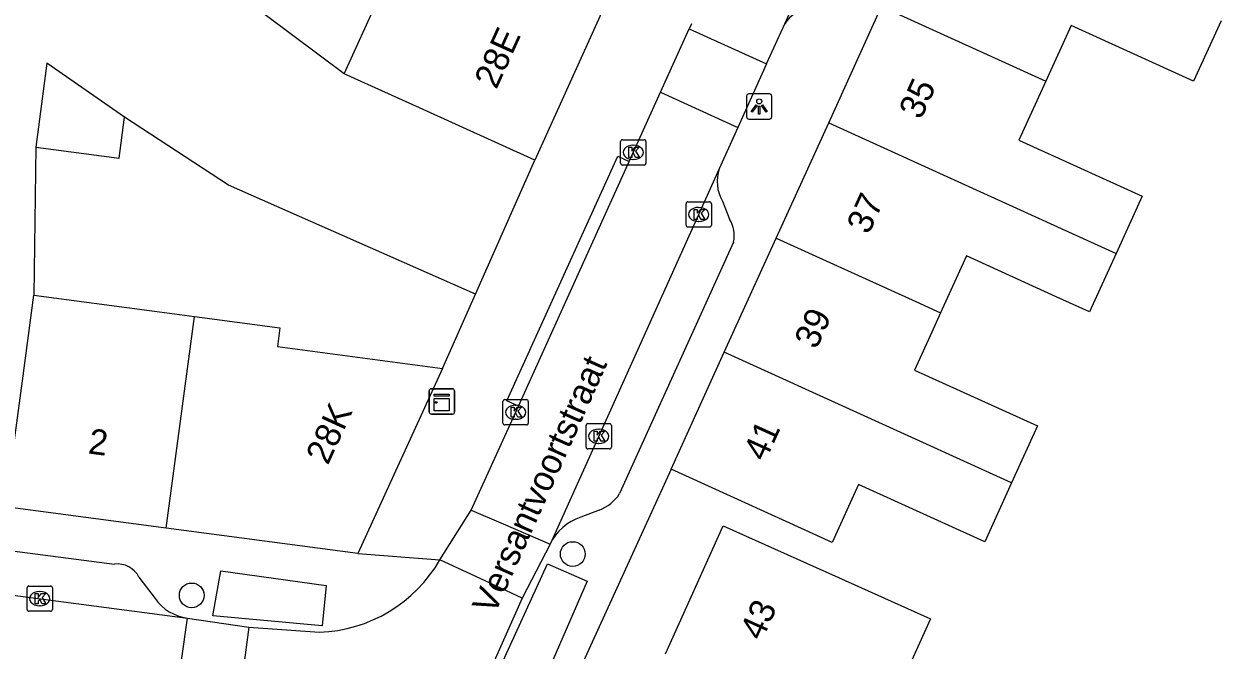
# Model space of a CAD drawing. Extents: x 161845 to 162341, y 381620 to 382158.
# Drawn here: x 162036.15 to 162083.32, y 381694.14 to 381718.91 of the extents above; entities that cross this region are included whole.
import ezdxf

# ---------------------------------------------------------------- set-up
doc = ezdxf.new("R2010")
doc.units = 0
for name, color, linetype in [('IMGEO_Boom', 7, 'Continuous'), ('IMGEO_Kast', 7, 'Continuous'), ('IMGEO_Kolk', 7, 'Continuous'), ('IMGEO_Lichtpunt', 7, 'Continuous'), ('IMGEO_Openbare_ruimte_label', 7, 'Continuous'), ('IMGEO_Pand', 7, 'Continuous'), ('IMGEO_Pand_nummerreeks', 7, 'Continuous'), ('IMGEO_Rijbaan_lokaal_open', 7, 'Continuous'), ('IMGEO_Voetpad_open', 7, 'Continuous')]:
    doc.layers.add(name, color=color, linetype=linetype)

msp = doc.modelspace()

# ---------------------------------------------------------------- linework, layer by layer
at = {"layer": 'IMGEO_Boom'}
for centre in [(162057.851, 381697.943), (162042.788, 381696.309)]:
    msp.add_circle(centre, 0.489, dxfattribs=at)
at = {"layer": 'IMGEO_Kast'}
for p, q in [((162052.176, 381703.553), (162052.176, 381704.394)), ((162052.176, 381704.394), (162052.176, 381703.553)), ((162052.251, 381704.478), (162053.092, 381704.478)), ((162053.092, 381704.478), (162052.251, 381704.478)), ((162053.176, 381704.403), (162053.176, 381703.562)), ((162053.176, 381703.562), (162053.176, 381704.403)), ((162053.101, 381703.478), (162052.26, 381703.478)), ((162052.26, 381703.478), (162053.101, 381703.478))]:
    msp.add_line(p, q, dxfattribs=at)
for points in [[(162052.371, 381704.268), (162052.971, 381704.268), (162052.971, 381704.183), (162052.371, 381704.183), (162052.371, 381704.268)], [(162052.371, 381704.093), (162052.971, 381704.093), (162052.971, 381703.604), (162052.371, 381703.604), (162052.371, 381704.093)]]:
    msp.add_lwpolyline(points, dxfattribs=at)
msp.add_circle((162052.455, 381703.942), 0.0377, dxfattribs=at)
for centre, start, end in [((162052.254, 381704.4), 92.4484, 184.2845), ((162052.254, 381704.4), 92.4484, 184.2845), ((162053.098, 381704.4), 2.4484, 94.2845), ((162053.098, 381704.4), 2.4484, 94.2845), ((162052.254, 381703.556), 182.4484, 274.2845), ((162052.254, 381703.556), 182.4484, 274.2845), ((162053.098, 381703.556), 272.4484, 4.2845), ((162053.098, 381703.556), 272.4484, 4.2845)]:
    msp.add_arc(centre, 0.0779, start, end, dxfattribs=at)
at = {"layer": 'IMGEO_Kolk'}
for p, q in [((162059.74, 381713.403), (162059.74, 381714.255)), ((162059.815, 381714.329), (162060.667, 381714.329)), ((162060.228, 381714.109), (162060.253, 381714.109)), ((162060.741, 381714.255), (162060.741, 381713.403)), ((162060.251, 381713.549), (162060.226, 381713.549)), ((162060.667, 381713.329), (162059.815, 381713.329)), ((162062.328, 381710.946), (162062.328, 381711.798)), ((162062.403, 381711.872), (162063.255, 381711.872)), ((162062.816, 381711.652), (162062.841, 381711.652)), ((162063.329, 381711.798), (162063.329, 381710.946)), ((162063.255, 381710.872), (162062.403, 381710.872)), ((162062.839, 381711.092), (162062.814, 381711.092)), ((162055.09, 381703.125), (162055.09, 381703.977)), ((162055.165, 381704.051), (162056.017, 381704.051)), ((162055.578, 381703.831), (162055.603, 381703.831)), ((162056.091, 381703.977), (162056.091, 381703.125)), ((162055.601, 381703.271), (162055.576, 381703.271)), ((162056.017, 381703.051), (162055.165, 381703.051)), ((162058.375, 381702.175), (162058.375, 381703.027)), ((162058.45, 381703.101), (162059.302, 381703.101)), ((162058.863, 381702.881), (162058.888, 381702.881)), ((162059.376, 381703.027), (162059.376, 381702.175)), ((162058.886, 381702.321), (162058.861, 381702.321)), ((162059.302, 381702.101), (162058.45, 381702.101)), ((162036.28, 381695.753), (162036.28, 381696.605)), ((162036.355, 381696.679), (162037.207, 381696.679)), ((162037.281, 381696.605), (162037.281, 381695.753)), ((162036.768, 381696.459), (162036.793, 381696.459)), ((162037.207, 381695.679), (162036.355, 381695.679)), ((162036.791, 381695.899), (162036.766, 381695.899))]:
    msp.add_line(p, q, dxfattribs=at)
for points in [[(162059.74, 381713.403), (162059.74, 381714.255)], [(162059.815, 381714.329), (162060.667, 381714.329)], [(162060.061, 381714.029), (162060.184, 381714.029), (162060.184, 381713.878), (162060.314, 381714.029), (162060.478, 381714.029), (162060.332, 381713.878), (162060.485, 381713.629), (162060.333, 381713.629), (162060.248, 381713.793), (162060.184, 381713.726), (162060.184, 381713.629), (162060.061, 381713.629), (162060.061, 381714.029)], [(162060.741, 381714.255), (162060.741, 381713.403)], [(162060.667, 381713.329), (162059.815, 381713.329)], [(162062.328, 381710.946), (162062.328, 381711.798)], [(162062.403, 381711.872), (162063.255, 381711.872)], [(162063.329, 381711.798), (162063.329, 381710.946)], [(162062.649, 381711.572), (162062.772, 381711.572), (162062.772, 381711.421), (162062.902, 381711.572), (162063.066, 381711.572), (162062.92, 381711.421), (162063.073, 381711.172), (162062.921, 381711.172), (162062.836, 381711.336), (162062.772, 381711.269), (162062.772, 381711.172), (162062.649, 381711.172), (162062.649, 381711.572)], [(162063.255, 381710.872), (162062.403, 381710.872)], [(162055.09, 381703.125), (162055.09, 381703.977)], [(162055.165, 381704.051), (162056.017, 381704.051)], [(162055.411, 381703.751), (162055.534, 381703.751), (162055.534, 381703.6), (162055.664, 381703.751), (162055.828, 381703.751), (162055.682, 381703.6), (162055.835, 381703.351), (162055.683, 381703.351), (162055.598, 381703.515), (162055.534, 381703.448), (162055.534, 381703.351), (162055.411, 381703.351), (162055.411, 381703.751)], [(162056.091, 381703.977), (162056.091, 381703.125)], [(162056.017, 381703.051), (162055.165, 381703.051)], [(162058.375, 381702.175), (162058.375, 381703.027)], [(162058.45, 381703.101), (162059.302, 381703.101)], [(162058.696, 381702.801), (162058.819, 381702.801), (162058.819, 381702.65), (162058.949, 381702.801), (162059.113, 381702.801), (162058.967, 381702.65), (162059.12, 381702.401), (162058.968, 381702.401), (162058.883, 381702.565), (162058.819, 381702.498), (162058.819, 381702.401), (162058.696, 381702.401), (162058.696, 381702.801)], [(162059.376, 381703.027), (162059.376, 381702.175)], [(162059.302, 381702.101), (162058.45, 381702.101)], [(162036.28, 381695.753), (162036.28, 381696.605)], [(162036.355, 381696.679), (162037.207, 381696.679)], [(162037.281, 381696.605), (162037.281, 381695.753)], [(162036.601, 381696.379), (162036.724, 381696.379), (162036.724, 381696.228), (162036.854, 381696.379), (162037.018, 381696.379), (162036.872, 381696.228), (162037.025, 381695.979), (162036.873, 381695.979), (162036.788, 381696.143), (162036.724, 381696.076), (162036.724, 381695.979), (162036.601, 381695.979), (162036.601, 381696.379)], [(162037.207, 381695.679), (162036.355, 381695.679)]]:
    msp.add_lwpolyline(points, dxfattribs=at)
for centre, start, end in [((162059.817, 381714.253), 91.552, 178.448), ((162059.817, 381714.253), 91.552, 178.448), ((162060.665, 381714.253), 1.552, 88.448), ((162060.665, 381714.253), 1.552, 88.448), ((162059.817, 381713.405), 181.552, 268.448), ((162059.817, 381713.405), 181.552, 268.448), ((162060.665, 381713.405), 271.552, 358.448), ((162060.665, 381713.405), 271.552, 358.448), ((162062.405, 381711.796), 91.552, 178.448), ((162062.405, 381711.796), 91.552, 178.448), ((162063.253, 381711.796), 1.552, 88.448), ((162063.253, 381711.796), 1.552, 88.448), ((162062.405, 381710.948), 181.552, 268.448), ((162062.405, 381710.948), 181.552, 268.448), ((162063.253, 381710.948), 271.552, 358.448), ((162063.253, 381710.948), 271.552, 358.448), ((162055.167, 381703.975), 91.552, 178.448), ((162055.167, 381703.975), 91.552, 178.448), ((162056.015, 381703.975), 1.552, 88.448), ((162056.015, 381703.975), 1.552, 88.448), ((162055.167, 381703.127), 181.552, 268.448), ((162055.167, 381703.127), 181.552, 268.448), ((162056.015, 381703.127), 271.552, 358.448), ((162056.015, 381703.127), 271.552, 358.448), ((162058.452, 381703.025), 91.552, 178.448), ((162058.452, 381703.025), 91.552, 178.448), ((162059.3, 381703.025), 1.552, 88.448), ((162059.3, 381703.025), 1.552, 88.448), ((162058.452, 381702.177), 181.552, 268.448), ((162058.452, 381702.177), 181.552, 268.448), ((162059.3, 381702.177), 271.552, 358.448), ((162059.3, 381702.177), 271.552, 358.448), ((162036.357, 381696.603), 91.552, 178.448), ((162036.357, 381696.603), 91.552, 178.448), ((162037.205, 381696.603), 1.552, 88.448), ((162037.205, 381696.603), 1.552, 88.448), ((162036.357, 381695.755), 181.552, 268.448), ((162036.357, 381695.755), 181.552, 268.448), ((162037.205, 381695.755), 271.552, 358.448), ((162037.205, 381695.755), 271.552, 358.448)]:
    msp.add_arc(centre, 0.0765, start, end, dxfattribs=at)
for centre, major_axis, ratio, start_param, end_param in [((162060.227, 381713.829), (-0.387, 0.002), 0.722429, 4.712389, 7.853982), ((162060.252, 381713.829), (-0.39, 0.002), 0.717154, 1.570796, 4.712389), ((162062.815, 381711.372), (-0.387, 0.002), 0.722429, 4.712389, 7.853982), ((162062.84, 381711.372), (-0.39, 0.002), 0.717154, 1.570796, 4.712389), ((162055.577, 381703.551), (-0.387, 0.002), 0.722429, 4.712389, 7.853982), ((162055.602, 381703.551), (-0.39, 0.002), 0.717154, 1.570796, 4.712389), ((162058.862, 381702.601), (-0.387, 0.002), 0.722429, 4.712389, 7.853982), ((162058.887, 381702.601), (-0.39, 0.002), 0.717154, 1.570796, 4.712389), ((162036.767, 381696.179), (-0.387, 0.002), 0.722429, 4.712389, 7.853982), ((162036.792, 381696.179), (-0.39, 0.002), 0.717154, 1.570796, 4.712389)]:
    msp.add_ellipse(centre, major_axis=major_axis, ratio=ratio, start_param=start_param, end_param=end_param, dxfattribs=at)
at = {"layer": 'IMGEO_Lichtpunt'}
for p, q in [((162064.721, 381716.045), (162064.721, 381715.238)), ((162064.721, 381716.045), (162064.721, 381715.238)), ((162065.623, 381716.14), (162064.815, 381716.14)), ((162065.623, 381716.14), (162064.815, 381716.14)), ((162065.717, 381715.238), (162065.717, 381716.045)), ((162065.717, 381715.238), (162065.717, 381716.045)), ((162064.815, 381715.144), (162065.623, 381715.144)), ((162064.815, 381715.144), (162065.623, 381715.144))]:
    msp.add_line(p, q, dxfattribs=at)
for points in [[(162065.095, 381715.709), (162065.134, 381715.681), (162064.946, 381715.419), (162064.908, 381715.446), (162065.095, 381715.709)], [(162065.197, 381715.661), (162065.244, 381715.661), (162065.244, 381715.339), (162065.197, 381715.339), (162065.197, 381715.661)], [(162065.307, 381715.681), (162065.345, 381715.708), (162065.532, 381715.446), (162065.493, 381715.418), (162065.307, 381715.681)]]:
    msp.add_lwpolyline(points, dxfattribs=at)
msp.add_circle((162065.22, 381715.843), 0.0994, dxfattribs=at)
for centre, start, end in [((162064.815, 381716.045), 90, 180), ((162064.815, 381716.045), 90, 180), ((162065.623, 381716.045), 0, 90), ((162065.623, 381716.045), 0, 90), ((162064.815, 381715.238), 180, 270), ((162064.815, 381715.238), 180, 270), ((162065.623, 381715.238), 270, 0), ((162065.623, 381715.238), 270, 360)]:
    msp.add_arc(centre, 0.0946, start, end, dxfattribs=at)
at = {"layer": 'IMGEO_Pand'}
for points in [[(162048.815, 381716.934), (162051.526, 381722.912), (162054.491, 381721.55), (162059.046, 381719.488)], [(162059.046, 381719.488), (162056.347, 381713.524)], [(162067.969, 381714.998), (162070.06, 381719.595)], [(162070.06, 381719.595), (162076.547, 381716.643)], [(162083.477, 381719.029), (162082.393, 381716.646), (162077.551, 381718.849), (162076.547, 381716.643)], [(162040.13, 381715.222), (162037.066, 381717.36), (162036.628, 381714.033)], [(162056.347, 381713.524), (162051.793, 381715.586), (162048.815, 381716.934)], [(162076.547, 381716.643), (162075.487, 381714.313), (162080.36, 381712.096), (162079.329, 381709.83)], [(162036.628, 381714.033), (162039.916, 381713.6), (162040.13, 381715.222)], [(162065.894, 381710.438), (162067.969, 381714.998)], [(162067.969, 381714.998), (162079.329, 381709.83)], [(162063.841, 381705.924), (162065.894, 381710.438)], [(162065.894, 381710.438), (162071.408, 381707.929), (162072.243, 381707.549), (162072.389, 381707.483)], [(162079.329, 381709.83), (162078.278, 381707.519), (162076.96, 381708.119), (162073.413, 381709.734), (162072.389, 381707.483)], [(162035.43, 381699.815), (162036.094, 381704.795), (162036.546, 381708.187)], [(162036.546, 381708.187), (162041.321, 381707.551), (162042.9, 381707.34)], [(162072.389, 381707.483), (162072.039, 381706.715), (162071.359, 381705.221), (162076.22, 381703.009), (162075.196, 381700.758)], [(162041.781, 381698.968), (162042.9, 381707.34)], [(162042.9, 381707.34), (162046.277, 381706.89), (162046.178, 381706.147), (162052.704, 381705.277)], [(162061.738, 381701.301), (162063.841, 381705.924)], [(162075.196, 381700.758), (162063.841, 381705.924)], [(162052.704, 381705.277), (162049.351, 381697.959)], [(162075.196, 381700.758), (162074.136, 381698.428), (162069.147, 381700.698), (162068.104, 381698.405), (162066.29, 381699.23), (162061.738, 381701.301)], [(162041.781, 381698.968), (162035.43, 381699.815)], [(162049.351, 381697.959), (162041.781, 381698.968)], [(162061.513, 381693.995), (162063.797, 381699.063), (162068.359, 381697.015), (162071.995, 381695.383), (162069.704, 381690.303)]]:
    msp.add_lwpolyline(points, dxfattribs=at)
at = {"layer": 'IMGEO_Rijbaan_lokaal_open'}
for points in [[(162066.227, 381718.911), (162074.46, 381737.176)], [(162048.815, 381716.934), (162042.565, 381721.62), (162043.634, 381723.976)], [(162061.316, 381716.204), (162062.449, 381718.709)], [(162062.541, 381718.913), (162062.449, 381718.709)], [(162062.449, 381718.709), (162065.512, 381717.324)], [(162065.512, 381717.324), (162066.227, 381718.911)], [(162065.512, 381717.324), (162064.381, 381714.817)], [(162060.08, 381713.471), (162061.316, 381716.204)], [(162061.316, 381716.204), (162064.381, 381714.817)], [(162054.002, 381708.216), (162044.24, 381712.529), (162040.13, 381715.222)], [(162064.381, 381714.817), (162063.642, 381713.177)], [(162036.628, 381714.033), (162036.546, 381708.187)], [(162054.002, 381708.216), (162056.347, 381713.524)], [(162055.703, 381703.794), (162060.08, 381713.471)], [(162063.642, 381713.177), (162056.954, 381698.339)], [(162053.839, 381699.673), (162055.703, 381703.794)], [(162052.602, 381697.712), (162053.839, 381699.673)], [(162053.839, 381699.673), (162055.094, 381699.135), (162056.954, 381698.339)], [(162016.905, 381698.798), (162042.617, 381695.408)], [(162056.954, 381698.339), (162055.845, 381696.201)], [(162055.845, 381696.201), (162054.025, 381697.049), (162052.602, 381697.712)], [(162055.845, 381696.201), (162050.769, 381684.752)], [(162042.152, 381692.068), (162042.384, 381693.733), (162042.617, 381695.408)], [(162042.617, 381695.408), (162045.045, 381695.054)], [(162045.045, 381695.054), (162044.822, 381693.364), (162044.609, 381691.743)], [(162045.045, 381695.054), (162047.839, 381694.849)]]:
    msp.add_lwpolyline(points, dxfattribs=at)
msp.add_arc((162047.622, 381700.603), 5.758, 272.1564, 329.863, dxfattribs=at)
at = {"layer": 'IMGEO_Voetpad_open'}
for points in [[(162055.703, 381703.794), (162055.249, 381704.002), (162059.626, 381713.679), (162060.08, 381713.471)], [(162063.766, 381711.904), (162064.049, 381711.181)], [(162064.205, 381710.281), (162059.703, 381700.334)], [(162052.704, 381705.277), (162054.002, 381708.216)], [(162061.738, 381701.301), (162055.986, 381688.68), (162052.997, 381681.186)], [(162018.283, 381700.334), (162039.735, 381697.544)], [(162058.893, 381699.683), (162058.171, 381699.401)], [(162049.351, 381697.959), (162052.602, 381697.712)], [(162058.423, 381696.876), (162056.625, 381692.742), (162054.959, 381693.408), (162056.858, 381697.554), (162058.423, 381696.876)], [(162040.702, 381697.028), (162041.34, 381696.18)], [(162043.937, 381697.283), (162048.103, 381696.704), (162047.945, 381695.104), (162043.628, 381695.504), (162043.937, 381697.283)]]:
    msp.add_lwpolyline(points, dxfattribs=at)
for centre, radius, start, end in [((162067.275, 381718.248), 1.24, 94.672, 147.6816), ((162065.103, 381712.677), 1.544, 161.0965, 210.0305), ((162063.06, 381710.546), 1.175, 346.9596, 32.7075), ((162058.321, 381701.224), 1.644, 290.3672, 327.2107), ((162058.781, 381697.474), 2.021, 107.5603, 154.6581), ((162039.855, 381696.605), 0.947, 26.5517, 97.2787), ((162042.879, 381697.283), 1.893, 215.6333, 262.0573)]:
    msp.add_arc(centre, radius, start, end, dxfattribs=at)

# ---------------------------------------------------------------- texts
at = {"layer": 'IMGEO_Openbare_ruimte_label'}
msp.add_text('Versantvoortstraat', height=1, rotation=65.8454, dxfattribs=at).set_placement((162054.755, 381695.505))
at = {"layer": 'IMGEO_Pand_nummerreeks'}
for s, rotation, p in [('28E', 65.6509, (162054.832, 381716.289)), ('35', 65.5401, (162071.613, 381715.088)), ('37', 65.5406, (162069.547, 381710.546)), ('39', 65.5406, (162067.481, 381706.003)), ('28K', 65.3834, (162048.17, 381701.431)), ('2', 352.4059, (162038.664, 381701.926)), ('41', 65.5401, (162065.461, 381701.564)), ('43', 65.7353, (162065.327, 381694.476))]:
    msp.add_text(s, height=1, rotation=rotation, dxfattribs=at).set_placement(p)

doc.saveas('drawing.dxf')
